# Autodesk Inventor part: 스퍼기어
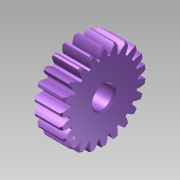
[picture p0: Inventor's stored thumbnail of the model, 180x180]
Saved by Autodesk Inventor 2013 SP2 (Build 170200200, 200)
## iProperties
Created: 2025-04
Part Number: 스퍼기어
Material: Generic
Document SubType Name: Modeling
Designer: i
Density: 1 g/cm^3
변환 표준: STEP AP214IS
전처리기: Build: 200, Release: 2013 SP2 Update 6 - Date: Thu 07/17/2014
전송 단위: 밀리미터
불확실성: 0.01
Author: i
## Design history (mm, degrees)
node "스퍼기어1"
node "솔리드1"
node "기준1"
